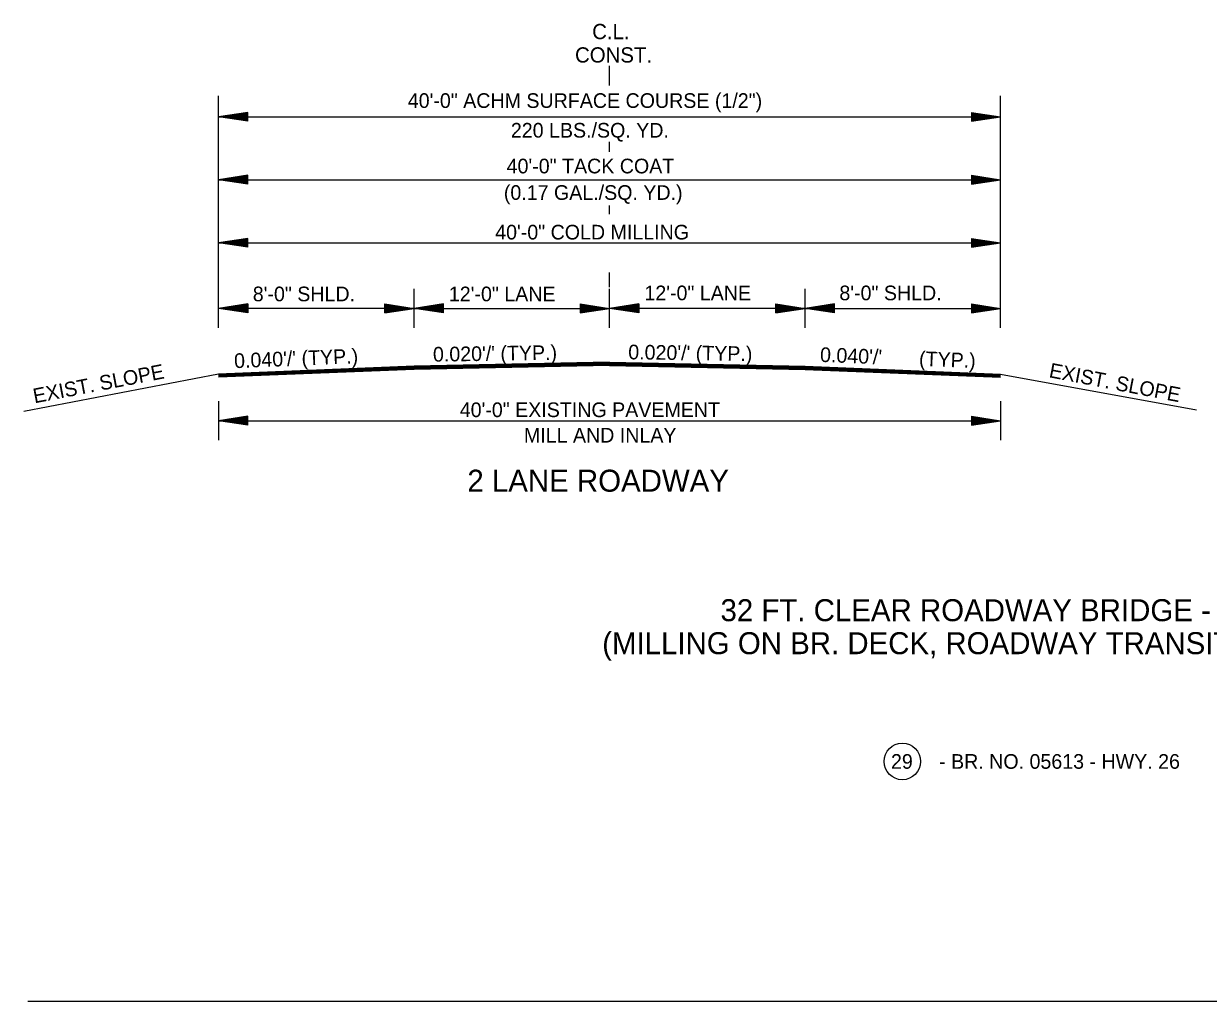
# Model space of a CAD drawing. Extents: x 545241 to 1930787, y -1971772 to 596640.
# Drawn here: x 546741 to 547347, y -1960905 to -1960405 of the extents above; entities that cross this region are included whole.
import ezdxf

# ---------------------------------------------------------------- set-up
doc = ezdxf.new("R2010")
doc.units = 0
doc.layers.add('R_Border', color=7, linetype='Continuous')
doc.layers.add('R_Draft', color=7, linetype='Continuous')

msp = doc.modelspace()

# ---------------------------------------------------------------- linework, layer by layer
at = {"layer": 'R_Border'}
for p, q in [((546940.32, -1960580.44), (546840.32, -1960584.44)), ((546940.32, -1960580.73), (546840.32, -1960584.73)), ((546940.32, -1960581.03), (546840.32, -1960585.03)), ((546940.32, -1960581.34), (546840.32, -1960585.34)), ((546940.32, -1960581.64), (546840.32, -1960585.64)), ((546940.32, -1960581.94), (546840.32, -1960585.94)), ((546940.32, -1960582.11), (546840.32, -1960586.11)), ((547140.32, -1960580.44), (547240.32, -1960584.44)), ((547140.32, -1960580.74), (547240.32, -1960584.74)), ((547140.32, -1960581.04), (547240.32, -1960585.04)), ((547140.32, -1960581.34), (547240.32, -1960585.34)), ((547140.32, -1960581.64), (547240.32, -1960585.64)), ((547140.32, -1960581.94), (547240.32, -1960585.94)), ((547140.32, -1960582.11), (547240.32, -1960586.11)), ((546742.77, -1960905.24), (547770.72, -1960905.24))]:
    msp.add_line(p, q, dxfattribs=at)
msp.add_circle((547190.03, -1960782.57), 9.34, dxfattribs=at)
at = {"layer": 'R_Draft'}
for p, q in [((547040.32, -1960436.86), (547040.32, -1960426.86)), ((546840.32, -1960560.83), (546840.32, -1960442.17)), ((547240.32, -1960560.83), (547240.32, -1960442.17)), ((546855.32, -1960450.66), (546840.32, -1960452.91)), ((546840.32, -1960452.91), (547240.32, -1960452.91)), ((546855.32, -1960455.16), (546840.32, -1960452.91)), ((546855.32, -1960451.03), (546842.82, -1960452.91)), ((546855.32, -1960454.78), (546842.82, -1960452.91)), ((546855.32, -1960451.41), (546845.4, -1960452.91)), ((546855.32, -1960454.4), (546845.4, -1960452.91)), ((546855.32, -1960451.79), (546847.9, -1960452.91)), ((546855.32, -1960454.02), (546847.9, -1960452.91)), ((546855.32, -1960452.17), (546850.44, -1960452.91)), ((546855.32, -1960453.63), (546850.44, -1960452.91)), ((546855.32, -1960452.55), (546852.95, -1960452.91)), ((546855.32, -1960453.26), (546852.95, -1960452.91)), ((546855.32, -1960455.16), (546855.32, -1960450.66)), ((547225.32, -1960450.66), (547240.32, -1960452.91)), ((547225.32, -1960450.66), (547225.32, -1960455.16)), ((547225.32, -1960451.03), (547237.81, -1960452.91)), ((547225.32, -1960451.41), (547235.23, -1960452.91)), ((547225.32, -1960451.79), (547232.73, -1960452.91)), ((547225.32, -1960452.18), (547230.19, -1960452.91)), ((547225.32, -1960452.55), (547227.69, -1960452.91)), ((547225.32, -1960455.16), (547240.32, -1960452.91)), ((547225.32, -1960453.64), (547230.19, -1960452.91)), ((547225.32, -1960454.4), (547235.23, -1960452.91)), ((547225.32, -1960454.78), (547237.81, -1960452.91)), ((547225.32, -1960454.02), (547232.73, -1960452.91)), ((547225.32, -1960453.26), (547227.69, -1960452.91)), ((547040.32, -1960470.79), (547040.32, -1960465.76)), ((546855.32, -1960482.8), (546840.32, -1960485.05)), ((546840.32, -1960485.05), (547240.32, -1960485.05)), ((546855.32, -1960487.3), (546840.32, -1960485.05)), ((546855.32, -1960483.18), (546842.82, -1960485.05)), ((546855.32, -1960486.93), (546842.82, -1960485.05)), ((546855.32, -1960483.56), (546845.4, -1960485.05)), ((546855.32, -1960486.55), (546845.4, -1960485.05)), ((546855.32, -1960483.94), (546847.9, -1960485.05)), ((546855.32, -1960486.17), (546847.9, -1960485.05)), ((546855.32, -1960484.32), (546850.44, -1960485.05)), ((546855.32, -1960485.78), (546850.44, -1960485.05)), ((546855.32, -1960484.7), (546852.95, -1960485.05)), ((546855.32, -1960485.41), (546852.95, -1960485.05)), ((546855.32, -1960487.3), (546855.32, -1960482.8)), ((547225.32, -1960482.8), (547240.32, -1960485.05)), ((547225.32, -1960482.8), (547225.32, -1960487.3)), ((547225.32, -1960483.18), (547237.81, -1960485.05)), ((547225.32, -1960483.56), (547235.23, -1960485.05)), ((547225.32, -1960483.94), (547232.73, -1960485.05)), ((547225.32, -1960484.33), (547230.19, -1960485.05)), ((547225.32, -1960484.7), (547227.69, -1960485.05)), ((547225.32, -1960487.3), (547240.32, -1960485.05)), ((547225.32, -1960485.79), (547230.19, -1960485.05)), ((547225.32, -1960486.55), (547235.23, -1960485.05)), ((547225.32, -1960486.93), (547237.81, -1960485.05)), ((547225.32, -1960486.17), (547232.73, -1960485.05)), ((547225.32, -1960485.41), (547227.69, -1960485.05)), ((547040.32, -1960502.64), (547040.32, -1960498.19)), ((546855.32, -1960515.04), (546840.32, -1960517.29)), ((546855.32, -1960515.42), (546842.82, -1960517.29)), ((546855.32, -1960515.8), (546845.4, -1960517.29)), ((546855.32, -1960516.17), (546847.9, -1960517.29)), ((546855.32, -1960516.56), (546850.44, -1960517.29)), ((546855.32, -1960516.94), (546852.95, -1960517.29)), ((546855.32, -1960519.54), (546855.32, -1960515.04)), ((547225.32, -1960515.04), (547240.32, -1960517.29)), ((547225.32, -1960515.04), (547225.32, -1960519.54)), ((547225.32, -1960515.42), (547237.81, -1960517.29)), ((547225.32, -1960515.8), (547235.23, -1960517.29)), ((547225.32, -1960516.17), (547232.73, -1960517.29)), ((547225.32, -1960516.56), (547230.19, -1960517.29)), ((547225.32, -1960516.94), (547227.69, -1960517.29)), ((546840.32, -1960517.29), (547240.32, -1960517.29)), ((546855.32, -1960519.54), (546840.32, -1960517.29)), ((546855.32, -1960519.17), (546842.82, -1960517.29)), ((546855.32, -1960518.78), (546845.4, -1960517.29)), ((546855.32, -1960518.41), (546847.9, -1960517.29)), ((546855.32, -1960518.02), (546850.44, -1960517.29)), ((546855.32, -1960517.64), (546852.95, -1960517.29)), ((547225.32, -1960519.54), (547240.32, -1960517.29)), ((547225.32, -1960518.03), (547230.19, -1960517.29)), ((547225.32, -1960518.78), (547235.23, -1960517.29)), ((547225.32, -1960519.17), (547237.81, -1960517.29)), ((547225.32, -1960518.41), (547232.73, -1960517.29)), ((547225.32, -1960517.64), (547227.69, -1960517.29)), ((547040.32, -1960540.05), (547040.32, -1960532.53)), ((546940.32, -1960560.83), (546940.32, -1960540.94)), ((547040.32, -1960560.83), (547040.32, -1960540.94)), ((547140.32, -1960560.83), (547140.32, -1960540.94)), ((546855.32, -1960548.58), (546840.32, -1960550.83)), ((546940.32, -1960550.83), (546840.32, -1960550.83)), ((546855.32, -1960553.08), (546840.32, -1960550.83)), ((546855.32, -1960548.95), (546842.82, -1960550.83)), ((546855.32, -1960552.7), (546842.82, -1960550.83)), ((546855.32, -1960549.34), (546845.4, -1960550.83)), ((546855.32, -1960552.32), (546845.4, -1960550.83)), ((546855.32, -1960549.71), (546847.9, -1960550.83)), ((546855.32, -1960551.95), (546847.9, -1960550.83)), ((546855.32, -1960550.1), (546850.44, -1960550.83)), ((546855.32, -1960551.56), (546850.44, -1960550.83)), ((546855.32, -1960550.48), (546852.95, -1960550.83)), ((546855.32, -1960551.18), (546852.95, -1960550.83)), ((546855.32, -1960548.58), (546855.32, -1960553.08)), ((546925.32, -1960548.58), (546940.32, -1960550.83)), ((546925.32, -1960553.08), (546925.32, -1960548.58)), ((546925.32, -1960548.95), (546937.81, -1960550.83)), ((546925.32, -1960549.34), (546935.23, -1960550.83)), ((546925.32, -1960549.71), (546932.73, -1960550.83)), ((546925.32, -1960550.09), (546930.19, -1960550.83)), ((546925.32, -1960550.48), (546927.69, -1960550.83)), ((546925.32, -1960553.08), (546940.32, -1960550.83)), ((546925.32, -1960551.56), (546930.19, -1960550.83)), ((546925.32, -1960552.32), (546935.23, -1960550.83)), ((546925.32, -1960552.7), (546937.81, -1960550.83)), ((546925.32, -1960551.95), (546932.73, -1960550.83)), ((546925.32, -1960551.18), (546927.69, -1960550.83)), ((546955.32, -1960548.58), (546940.32, -1960550.83)), ((546955.32, -1960553.08), (546940.32, -1960550.83)), ((546940.32, -1960550.83), (547040.32, -1960550.83)), ((546955.32, -1960548.95), (546942.82, -1960550.83)), ((546955.32, -1960552.7), (546942.82, -1960550.83)), ((546955.32, -1960549.34), (546945.4, -1960550.83)), ((546955.32, -1960552.32), (546945.4, -1960550.83)), ((546955.32, -1960549.71), (546947.9, -1960550.83)), ((546955.32, -1960551.95), (546947.9, -1960550.83)), ((546955.32, -1960550.09), (546950.44, -1960550.83)), ((546955.32, -1960551.56), (546950.44, -1960550.83)), ((546955.32, -1960550.48), (546952.95, -1960550.83)), ((546955.32, -1960551.18), (546952.95, -1960550.83)), ((546955.32, -1960553.08), (546955.32, -1960548.58)), ((547025.32, -1960548.58), (547040.32, -1960550.83)), ((547025.32, -1960548.58), (547025.32, -1960553.08)), ((547025.32, -1960548.95), (547037.81, -1960550.83)), ((547025.32, -1960549.34), (547035.23, -1960550.83)), ((547025.32, -1960549.71), (547032.73, -1960550.83)), ((547025.32, -1960550.1), (547030.19, -1960550.83)), ((547025.32, -1960550.48), (547027.69, -1960550.83)), ((547025.32, -1960553.08), (547040.32, -1960550.83)), ((547025.32, -1960551.56), (547030.19, -1960550.83)), ((547025.32, -1960552.32), (547035.23, -1960550.83)), ((547025.32, -1960552.7), (547037.81, -1960550.83)), ((547025.32, -1960551.95), (547032.73, -1960550.83)), ((547025.32, -1960551.18), (547027.69, -1960550.83)), ((547055.32, -1960548.58), (547040.32, -1960550.83)), ((547140.32, -1960550.83), (547040.32, -1960550.83)), ((547055.32, -1960553.08), (547040.32, -1960550.83)), ((547055.32, -1960548.95), (547042.82, -1960550.83)), ((547055.32, -1960552.7), (547042.82, -1960550.83)), ((547055.32, -1960549.34), (547045.4, -1960550.83)), ((547055.32, -1960552.32), (547045.4, -1960550.83)), ((547055.32, -1960549.71), (547047.9, -1960550.83)), ((547055.32, -1960551.95), (547047.9, -1960550.83)), ((547055.32, -1960550.1), (547050.44, -1960550.83)), ((547055.32, -1960551.56), (547050.44, -1960550.83)), ((547055.32, -1960550.48), (547052.95, -1960550.83)), ((547055.32, -1960551.18), (547052.95, -1960550.83)), ((547055.32, -1960548.58), (547055.32, -1960553.08)), ((547125.32, -1960548.58), (547140.32, -1960550.83)), ((547125.32, -1960553.08), (547125.32, -1960548.58)), ((547125.32, -1960548.95), (547137.81, -1960550.83)), ((547125.32, -1960549.34), (547135.23, -1960550.83)), ((547125.32, -1960549.71), (547132.73, -1960550.83)), ((547125.32, -1960550.09), (547130.19, -1960550.83)), ((547125.32, -1960550.48), (547127.69, -1960550.83)), ((547125.32, -1960553.08), (547140.32, -1960550.83)), ((547125.32, -1960551.56), (547130.19, -1960550.83)), ((547125.32, -1960552.32), (547135.23, -1960550.83)), ((547125.32, -1960552.7), (547137.81, -1960550.83)), ((547125.32, -1960551.95), (547132.73, -1960550.83)), ((547125.32, -1960551.18), (547127.69, -1960550.83)), ((547155.32, -1960548.58), (547140.32, -1960550.83)), ((547140.32, -1960550.83), (547240.32, -1960550.83)), ((547155.32, -1960553.08), (547140.32, -1960550.83)), ((547155.32, -1960548.95), (547142.82, -1960550.83)), ((547155.32, -1960552.7), (547142.82, -1960550.83)), ((547155.32, -1960549.34), (547145.4, -1960550.83)), ((547155.32, -1960552.32), (547145.4, -1960550.83)), ((547155.32, -1960549.71), (547147.9, -1960550.83)), ((547155.32, -1960551.95), (547147.9, -1960550.83)), ((547155.32, -1960550.09), (547150.44, -1960550.83)), ((547155.32, -1960551.56), (547150.44, -1960550.83)), ((547155.32, -1960550.48), (547152.95, -1960550.83)), ((547155.32, -1960551.18), (547152.95, -1960550.83)), ((547155.32, -1960553.08), (547155.32, -1960548.58)), ((547225.32, -1960548.58), (547240.32, -1960550.83)), ((547225.32, -1960548.58), (547225.32, -1960553.08)), ((547225.32, -1960548.95), (547237.81, -1960550.83)), ((547225.32, -1960549.34), (547235.23, -1960550.83)), ((547225.32, -1960549.71), (547232.73, -1960550.83)), ((547225.32, -1960550.1), (547230.19, -1960550.83)), ((547225.32, -1960550.48), (547227.69, -1960550.83)), ((547225.32, -1960553.08), (547240.32, -1960550.83)), ((547225.32, -1960551.56), (547230.19, -1960550.83)), ((547225.32, -1960552.32), (547235.23, -1960550.83)), ((547225.32, -1960552.7), (547237.81, -1960550.83)), ((547225.32, -1960551.95), (547232.73, -1960550.83)), ((547225.32, -1960551.18), (547227.69, -1960550.83)), ((547040.32, -1960578.44), (546940.32, -1960580.44)), ((547040.31, -1960578.74), (546940.32, -1960580.74)), ((547040.32, -1960579.04), (546940.32, -1960581.04)), ((547040.34, -1960579.34), (546940.32, -1960581.34)), ((547040.34, -1960579.64), (546940.32, -1960581.64)), ((547040.35, -1960579.94), (546940.32, -1960581.94)), ((547040.35, -1960580.11), (546940.32, -1960582.11)), ((547040.28, -1960580.11), (547140.32, -1960582.11)), ((547040.29, -1960579.64), (547140.32, -1960581.64)), ((547040.29, -1960579.94), (547140.32, -1960581.94)), ((547040.3, -1960579.34), (547140.32, -1960581.34)), ((547040.31, -1960578.74), (547140.32, -1960580.74)), ((547040.31, -1960579.04), (547140.32, -1960581.04)), ((547040.32, -1960578.44), (547140.32, -1960580.44)), ((546840.32, -1960584.44), (546740.68, -1960603.57)), ((547240.32, -1960584.44), (547340.39, -1960602.81)), ((546840.32, -1960598.29), (546840.32, -1960618.29)), ((547240.32, -1960598.29), (547240.32, -1960618.29)), ((546855.32, -1960606.04), (546840.32, -1960608.29)), ((546855.32, -1960606.42), (546842.82, -1960608.29)), ((546855.32, -1960606.8), (546845.4, -1960608.29)), ((546855.32, -1960607.18), (546847.9, -1960608.29)), ((546855.32, -1960607.56), (546850.44, -1960608.29)), ((546855.32, -1960607.94), (546852.95, -1960608.29)), ((546855.32, -1960610.54), (546855.32, -1960606.04)), ((547225.32, -1960606.04), (547240.32, -1960608.29)), ((547225.32, -1960606.04), (547225.32, -1960610.54)), ((547225.32, -1960606.42), (547237.81, -1960608.29)), ((547225.32, -1960606.8), (547235.23, -1960608.29)), ((547225.32, -1960607.18), (547232.73, -1960608.29)), ((547225.32, -1960607.57), (547230.19, -1960608.29)), ((547225.32, -1960607.94), (547227.69, -1960608.29)), ((546840.32, -1960608.29), (547240.32, -1960608.29)), ((546855.32, -1960610.54), (546840.32, -1960608.29)), ((546855.32, -1960610.17), (546842.82, -1960608.29)), ((546855.32, -1960609.79), (546845.4, -1960608.29)), ((546855.32, -1960609.41), (546847.9, -1960608.29)), ((546855.32, -1960609.02), (546850.44, -1960608.29)), ((546855.32, -1960608.65), (546852.95, -1960608.29)), ((547225.32, -1960610.54), (547240.32, -1960608.29)), ((547225.32, -1960609.03), (547230.19, -1960608.29)), ((547225.32, -1960609.79), (547235.23, -1960608.29)), ((547225.32, -1960610.17), (547237.81, -1960608.29)), ((547225.32, -1960609.41), (547232.73, -1960608.29)), ((547225.32, -1960608.65), (547227.69, -1960608.29))]:
    msp.add_line(p, q, dxfattribs=at)

# ---------------------------------------------------------------- texts
for s, height, p in [('C.L.', 7.8, (547031.42, -1960413.17)), ('CONST.', 7.8, (547022.64, -1960425.13)), ('40\'-0" ACHM SURFACE COURSE (1/2")', 7.5, (546937.12, -1960448.33)), ('220 LBS./SQ. YD. ', 7.5, (546989.83, -1960463.51)), ('40\'-0" TACK COAT', 7.5, (546987.67, -1960481.8)), ('(0.17 GAL./SQ. YD.)', 7.5, (546986.23, -1960495.35)), ('40\'-0" COLD MILLING', 7.5, (546981.82, -1960515.62)), ('8\'-0" SHLD.', 7.5, (546857.84, -1960547.22)), ('12\'-0" LANE', 7.5, (546958.13, -1960547.22)), ('12\'-0" LANE', 7.5, (547058.13, -1960546.7)), ('8\'-0" SHLD.', 7.5, (547157.84, -1960546.7)), ('40\'-0" EXISTING PAVEMENT', 7.5, (546963.69, -1960606.46)), ('MILL AND INLAY', 7.5, (546996.5, -1960619.47)), ('2 LANE ROADWAY', 11.25, (546967.59, -1960644.61)), ('32 FT. CLEAR ROADWAY BRIDGE - POLYMER OVERLAY', 11.25, (547097.04, -1960710.84)), ('(MILLING ON BR. DECK, ROADWAY TRANSITIONS, AND NEW GUARDRAIL)', 11.25, (547036.54, -1960727.71)), ('29', 7.5, (547184.22, -1960786.32)), ('- BR. NO. 05613 - HWY. 26', 7.5, (547208.83, -1960786.32))]:
    msp.add_text(s, height=height, dxfattribs=at).set_placement(p)
for s, rotation, p in [("0.040'/' (TYP.)", 2.29061, (546848.43, -1960581.44)), ("0.020'/' (TYP.)", 0.87191, (546950.04, -1960578.11)), ("0.020'/' (TYP.)", 359.12809, (547049.82, -1960576.88)), ("0.040'/' ", 357.70939, (547147.83, -1960578.2)), ('(TYP.)', 357.70939, (547198.46, -1960580.23)), ('EXIST. SLOPE', 10.88286, (546746.23, -1960599.43)), ('EXIST. SLOPE', 349.11714, (547264.7, -1960586.03))]:
    msp.add_text(s, height=7.5, rotation=rotation, dxfattribs=at).set_placement(p)

doc.saveas('drawing.dxf')
